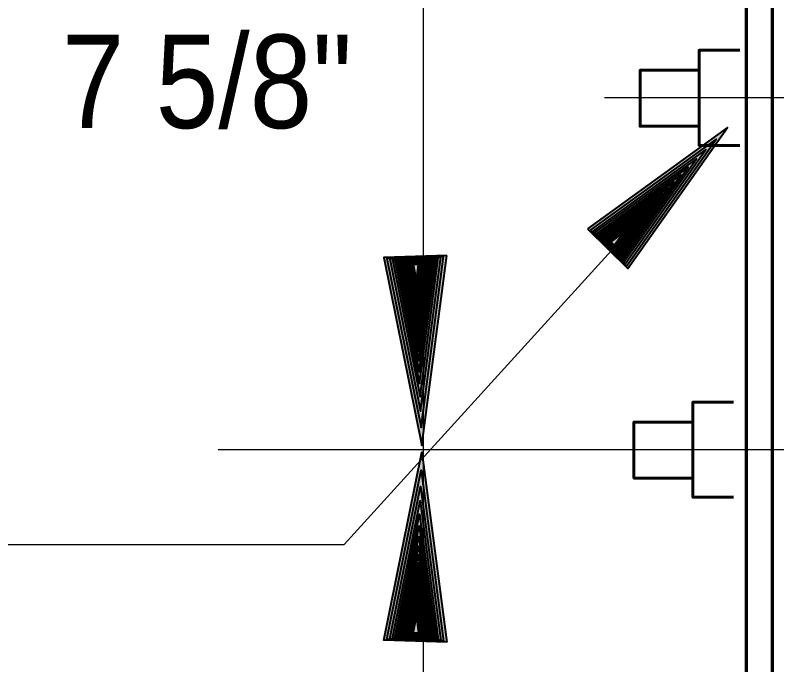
# Model space of a CAD drawing. Extents: x 856.9 to 891.7, y -2278.5 to -2254.7.
# Drawn here: x 863.098 to 864.144, y -2259.969 to -2259.076 of the extents above; entities that cross this region are included whole.
import ezdxf

# ---------------------------------------------------------------- set-up
doc = ezdxf.new("R2010")
doc.units = 0
doc.header["$LTSCALE"] = 0.051
doc.layers.add('1', color=7, linetype='Continuous', lineweight=70)
doc.layers.add('3', color=7, linetype='Continuous', lineweight=40)

msp = doc.modelspace()

# ---------------------------------------------------------------- hatches: boundary and pattern name
at = {"layer": '3'}
for points in [[(863.8845, -2259.36942), (863.94008, -2259.42425), (864.07683, -2259.23025), (864.07683, -2259.23025)], [(863.88808, -2259.37133), (863.938, -2259.42075), (864.06117, -2259.24625), (864.06117, -2259.24625)], [(863.89133, -2259.37317), (863.93617, -2259.41758), (864.047, -2259.2605), (864.047, -2259.2605)], [(863.89408, -2259.37475), (863.93442, -2259.41467), (864.03425, -2259.27333), (864.03425, -2259.27333)], [(863.8965, -2259.37625), (863.933, -2259.41208), (864.02275, -2259.28492), (864.02275, -2259.28492)], [(863.899, -2259.37742), (863.93175, -2259.40983), (864.0125, -2259.29533), (864.0125, -2259.29533)], [(863.90108, -2259.37875), (863.9305, -2259.40792), (864.00325, -2259.30475), (864.00325, -2259.30475)], [(863.903, -2259.37958), (863.92933, -2259.406), (863.99475, -2259.31325), (863.99475, -2259.31325)], [(863.90442, -2259.38067), (863.92858, -2259.40425), (863.98733, -2259.32083), (863.98733, -2259.32083)], [(863.90608, -2259.3815), (863.92783, -2259.40283), (863.98058, -2259.32767), (863.98058, -2259.32767)], [(863.9075, -2259.38225), (863.92683, -2259.40133), (863.9745, -2259.33392), (863.9745, -2259.33392)], [(863.90875, -2259.38308), (863.92608, -2259.40017), (863.96908, -2259.3395), (863.96908, -2259.3395)], [(863.90983, -2259.38358), (863.9255, -2259.39908), (863.964, -2259.3445), (863.964, -2259.3445)], [(863.91092, -2259.38408), (863.92492, -2259.39817), (863.95967, -2259.34875), (863.95967, -2259.34875)], [(863.91175, -2259.38458), (863.92442, -2259.39725), (863.95558, -2259.35283), (863.95558, -2259.35283)], [(863.9125, -2259.38508), (863.924, -2259.3965), (863.95217, -2259.35658), (863.95217, -2259.35658)], [(863.91333, -2259.38558), (863.92367, -2259.39583), (863.94892, -2259.35983), (863.94892, -2259.35983)], [(863.91392, -2259.386), (863.92317, -2259.39508), (863.94608, -2259.36275), (863.94608, -2259.36275)], [(863.9145, -2259.386), (863.92275, -2259.3945), (863.94333, -2259.36525), (863.94333, -2259.36525)], [(863.915, -2259.38633), (863.9225, -2259.39383), (863.94108, -2259.3675), (863.94108, -2259.3675)], [(863.91542, -2259.38633), (863.92225, -2259.39308), (863.93875, -2259.3695), (863.93875, -2259.3695)], [(863.91583, -2259.38683), (863.92192, -2259.39275), (863.93683, -2259.3715), (863.93683, -2259.3715)], [(863.91625, -2259.387), (863.92175, -2259.39233), (863.93533, -2259.37333), (863.93533, -2259.37333)], [(863.91658, -2259.38717), (863.9215, -2259.392), (863.93367, -2259.37475), (863.93367, -2259.37475)], [(863.69117, -2259.40608), (863.6045, -2259.409), (863.65667, -2259.66742), (863.65667, -2259.66742)], [(863.68683, -2259.40733), (863.60883, -2259.41008), (863.65583, -2259.64267), (863.65583, -2259.64267)], [(863.68292, -2259.40858), (863.61283, -2259.41092), (863.65508, -2259.62025), (863.65508, -2259.62025)], [(863.6795, -2259.40958), (863.61642, -2259.41175), (863.65442, -2259.60025), (863.65442, -2259.60025)], [(863.6765, -2259.4105), (863.61967, -2259.41242), (863.65383, -2259.58217), (863.65383, -2259.58217)], [(863.67358, -2259.41158), (863.6225, -2259.41317), (863.65333, -2259.56592), (863.65333, -2259.56592)], [(863.671, -2259.41225), (863.62508, -2259.41375), (863.65283, -2259.55117), (863.65283, -2259.55117)], [(863.66883, -2259.41308), (863.62733, -2259.41433), (863.65233, -2259.53792), (863.65233, -2259.53792)], [(863.66683, -2259.4135), (863.62942, -2259.41483), (863.65183, -2259.52617), (863.65183, -2259.52617)], [(863.66483, -2259.41425), (863.63117, -2259.41542), (863.6515, -2259.51533), (863.6515, -2259.51533)], [(863.66333, -2259.41467), (863.633, -2259.41575), (863.65125, -2259.50575), (863.65125, -2259.50575)], [(863.66175, -2259.41517), (863.63458, -2259.41617), (863.65083, -2259.49717), (863.65083, -2259.49717)], [(863.66042, -2259.41558), (863.63592, -2259.41642), (863.65058, -2259.48925), (863.65058, -2259.48925)], [(863.65917, -2259.41617), (863.63708, -2259.41667), (863.65042, -2259.48233), (863.65042, -2259.48233)], [(863.65808, -2259.41633), (863.63825, -2259.417), (863.65025, -2259.47608), (863.65025, -2259.47608)], [(863.65708, -2259.41675), (863.63925, -2259.41717), (863.64992, -2259.47042), (863.64992, -2259.47042)], [(863.65617, -2259.41692), (863.64008, -2259.4175), (863.64975, -2259.46533), (863.64975, -2259.46533)], [(863.65533, -2259.41708), (863.64092, -2259.41767), (863.64958, -2259.46075), (863.64958, -2259.46075)], [(863.65492, -2259.4175), (863.64175, -2259.41775), (863.64958, -2259.45667), (863.64958, -2259.45667)], [(863.65433, -2259.41767), (863.6425, -2259.41808), (863.6495, -2259.453), (863.6495, -2259.453)], [(863.65383, -2259.418), (863.64325, -2259.41842), (863.64967, -2259.44975), (863.64967, -2259.44975)], [(863.65325, -2259.418), (863.64383, -2259.41842), (863.6495, -2259.44667), (863.6495, -2259.44667)], [(863.65275, -2259.41817), (863.64425, -2259.4185), (863.64925, -2259.44392), (863.64925, -2259.44392)], [(863.65233, -2259.41842), (863.64475, -2259.41858), (863.64933, -2259.44158), (863.64933, -2259.44158)], [(863.69117, -2259.93775), (863.6045, -2259.93483), (863.65667, -2259.67642), (863.65667, -2259.67642)], [(863.68683, -2259.9365), (863.60883, -2259.93375), (863.65583, -2259.70117), (863.65583, -2259.70117)], [(863.68292, -2259.93525), (863.61283, -2259.93292), (863.65508, -2259.72358), (863.65508, -2259.72358)], [(863.6795, -2259.93425), (863.61642, -2259.93208), (863.65442, -2259.74358), (863.65442, -2259.74358)], [(863.6765, -2259.93333), (863.61967, -2259.93142), (863.65383, -2259.76167), (863.65383, -2259.76167)], [(863.67358, -2259.93225), (863.6225, -2259.93067), (863.65333, -2259.77792), (863.65333, -2259.77792)], [(863.671, -2259.93158), (863.62508, -2259.93008), (863.65283, -2259.79267), (863.65283, -2259.79267)], [(863.66883, -2259.93075), (863.62733, -2259.9295), (863.65233, -2259.80592), (863.65233, -2259.80592)], [(863.66683, -2259.93033), (863.62942, -2259.929), (863.65183, -2259.81767), (863.65183, -2259.81767)], [(863.66483, -2259.92958), (863.63117, -2259.92842), (863.6515, -2259.8285), (863.6515, -2259.8285)], [(863.66333, -2259.92917), (863.633, -2259.92808), (863.65125, -2259.83808), (863.65125, -2259.83808)], [(863.66175, -2259.92867), (863.63458, -2259.92767), (863.65083, -2259.84667), (863.65083, -2259.84667)], [(863.66042, -2259.92825), (863.63592, -2259.92742), (863.65058, -2259.85458), (863.65058, -2259.85458)], [(863.65917, -2259.92767), (863.63708, -2259.92717), (863.65042, -2259.8615), (863.65042, -2259.8615)], [(863.65808, -2259.9275), (863.63825, -2259.92683), (863.65025, -2259.86775), (863.65025, -2259.86775)], [(863.65708, -2259.92708), (863.63925, -2259.92667), (863.64992, -2259.87342), (863.64992, -2259.87342)], [(863.65617, -2259.92692), (863.64008, -2259.92633), (863.64975, -2259.8785), (863.64975, -2259.8785)], [(863.65533, -2259.92675), (863.64092, -2259.92617), (863.64958, -2259.88308), (863.64958, -2259.88308)], [(863.65492, -2259.92633), (863.64175, -2259.92608), (863.64958, -2259.88717), (863.64958, -2259.88717)], [(863.65433, -2259.92617), (863.6425, -2259.92575), (863.6495, -2259.89083), (863.6495, -2259.89083)], [(863.65383, -2259.92583), (863.64325, -2259.92542), (863.64967, -2259.89408), (863.64967, -2259.89408)], [(863.65325, -2259.92583), (863.64383, -2259.92542), (863.6495, -2259.89717), (863.6495, -2259.89717)], [(863.65275, -2259.92567), (863.64425, -2259.92533), (863.64925, -2259.89992), (863.64925, -2259.89992)], [(863.65233, -2259.92542), (863.64475, -2259.92525), (863.64933, -2259.90225), (863.64933, -2259.90225)]]:
    msp.add_hatch(color=256, dxfattribs=at).paths.add_polyline_path(points)

# ---------------------------------------------------------------- linework, layer by layer
at = {"layer": '1', "lineweight": 25}
for p, q in [((863.65917, -2260.57142), (863.65917, -2258.18292)), ((866.58492, -2259.18958), (863.90775, -2259.18958)), ((863.96775, -2259.34375), (863.55, -2259.80367)), ((865.83625, -2259.67342), (863.37692, -2259.67342)), ((862.061, -2259.80367), (863.55, -2259.80367))]:
    msp.add_line(p, q, dxfattribs=at)
at = {"layer": '1'}
msp.add_line((864.10225, -2258.59408), (864.10225, -2260.75108), dxfattribs=at)
msp.add_lwpolyline([(864.13817, -2258.59408), (864.13817, -2260.75108), (864.10225, -2260.75108)], dxfattribs=at)
at = {"layer": '1', "lineweight": 60}
for points in [[(864.0935, -2259.12392), (864.03775, -2259.12392), (864.03775, -2259.25475), (864.0935, -2259.25475)], [(864.03775, -2259.15142), (863.95675, -2259.15142), (863.95675, -2259.2285), (864.03775, -2259.2285)], [(864.085, -2259.60767), (864.02925, -2259.60767), (864.02925, -2259.7385), (864.085, -2259.7385)], [(864.02925, -2259.63517), (863.94825, -2259.63517), (863.94825, -2259.71225), (864.02925, -2259.71225)]]:
    msp.add_lwpolyline(points, dxfattribs=at)
at = {"layer": '3'}
for points in [[(863.8845, -2259.36942), (863.94008, -2259.42425), (864.07683, -2259.23025), (864.07683, -2259.23025)], [(863.88808, -2259.37133), (863.938, -2259.42075), (864.06117, -2259.24625), (864.06117, -2259.24625)], [(863.89133, -2259.37317), (863.93617, -2259.41758), (864.047, -2259.2605), (864.047, -2259.2605)], [(863.89408, -2259.37475), (863.93442, -2259.41467), (864.03425, -2259.27333), (864.03425, -2259.27333)], [(863.8965, -2259.37625), (863.933, -2259.41208), (864.02275, -2259.28492), (864.02275, -2259.28492)], [(863.899, -2259.37742), (863.93175, -2259.40983), (864.0125, -2259.29533), (864.0125, -2259.29533)], [(863.90108, -2259.37875), (863.9305, -2259.40792), (864.00325, -2259.30475), (864.00325, -2259.30475)], [(863.903, -2259.37958), (863.92933, -2259.406), (863.99475, -2259.31325), (863.99475, -2259.31325)], [(863.90442, -2259.38067), (863.92858, -2259.40425), (863.98733, -2259.32083), (863.98733, -2259.32083)], [(863.90608, -2259.3815), (863.92783, -2259.40283), (863.98058, -2259.32767), (863.98058, -2259.32767)], [(863.9075, -2259.38225), (863.92683, -2259.40133), (863.9745, -2259.33392), (863.9745, -2259.33392)], [(863.90875, -2259.38308), (863.92608, -2259.40017), (863.96908, -2259.3395), (863.96908, -2259.3395)], [(863.90983, -2259.38358), (863.9255, -2259.39908), (863.964, -2259.3445), (863.964, -2259.3445)], [(863.91092, -2259.38408), (863.92492, -2259.39817), (863.95967, -2259.34875), (863.95967, -2259.34875)], [(863.91175, -2259.38458), (863.92442, -2259.39725), (863.95558, -2259.35283), (863.95558, -2259.35283)], [(863.9125, -2259.38508), (863.924, -2259.3965), (863.95217, -2259.35658), (863.95217, -2259.35658)], [(863.91333, -2259.38558), (863.92367, -2259.39583), (863.94892, -2259.35983), (863.94892, -2259.35983)], [(863.91392, -2259.386), (863.92317, -2259.39508), (863.94608, -2259.36275), (863.94608, -2259.36275)], [(863.9145, -2259.386), (863.92275, -2259.3945), (863.94333, -2259.36525), (863.94333, -2259.36525)], [(863.915, -2259.38633), (863.9225, -2259.39383), (863.94108, -2259.3675), (863.94108, -2259.3675)], [(863.91542, -2259.38633), (863.92225, -2259.39308), (863.93875, -2259.3695), (863.93875, -2259.3695)], [(863.91583, -2259.38683), (863.92192, -2259.39275), (863.93683, -2259.3715), (863.93683, -2259.3715)], [(863.91625, -2259.387), (863.92175, -2259.39233), (863.93533, -2259.37333), (863.93533, -2259.37333)], [(863.91658, -2259.38717), (863.9215, -2259.392), (863.93367, -2259.37475), (863.93367, -2259.37475)], [(863.69117, -2259.40608), (863.6045, -2259.409), (863.65667, -2259.66742), (863.65667, -2259.66742)], [(863.68683, -2259.40733), (863.60883, -2259.41008), (863.65583, -2259.64267), (863.65583, -2259.64267)], [(863.68292, -2259.40858), (863.61283, -2259.41092), (863.65508, -2259.62025), (863.65508, -2259.62025)], [(863.6795, -2259.40958), (863.61642, -2259.41175), (863.65442, -2259.60025), (863.65442, -2259.60025)], [(863.6765, -2259.4105), (863.61967, -2259.41242), (863.65383, -2259.58217), (863.65383, -2259.58217)], [(863.67358, -2259.41158), (863.6225, -2259.41317), (863.65333, -2259.56592), (863.65333, -2259.56592)], [(863.671, -2259.41225), (863.62508, -2259.41375), (863.65283, -2259.55117), (863.65283, -2259.55117)], [(863.66883, -2259.41308), (863.62733, -2259.41433), (863.65233, -2259.53792), (863.65233, -2259.53792)], [(863.66683, -2259.4135), (863.62942, -2259.41483), (863.65183, -2259.52617), (863.65183, -2259.52617)], [(863.66483, -2259.41425), (863.63117, -2259.41542), (863.6515, -2259.51533), (863.6515, -2259.51533)], [(863.66333, -2259.41467), (863.633, -2259.41575), (863.65125, -2259.50575), (863.65125, -2259.50575)], [(863.66175, -2259.41517), (863.63458, -2259.41617), (863.65083, -2259.49717), (863.65083, -2259.49717)], [(863.66042, -2259.41558), (863.63592, -2259.41642), (863.65058, -2259.48925), (863.65058, -2259.48925)], [(863.65917, -2259.41617), (863.63708, -2259.41667), (863.65042, -2259.48233), (863.65042, -2259.48233)], [(863.65808, -2259.41633), (863.63825, -2259.417), (863.65025, -2259.47608), (863.65025, -2259.47608)], [(863.65708, -2259.41675), (863.63925, -2259.41717), (863.64992, -2259.47042), (863.64992, -2259.47042)], [(863.65617, -2259.41692), (863.64008, -2259.4175), (863.64975, -2259.46533), (863.64975, -2259.46533)], [(863.65533, -2259.41708), (863.64092, -2259.41767), (863.64958, -2259.46075), (863.64958, -2259.46075)], [(863.65492, -2259.4175), (863.64175, -2259.41775), (863.64958, -2259.45667), (863.64958, -2259.45667)], [(863.65433, -2259.41767), (863.6425, -2259.41808), (863.6495, -2259.453), (863.6495, -2259.453)], [(863.65383, -2259.418), (863.64325, -2259.41842), (863.64967, -2259.44975), (863.64967, -2259.44975)], [(863.65325, -2259.418), (863.64383, -2259.41842), (863.6495, -2259.44667), (863.6495, -2259.44667)], [(863.65275, -2259.41817), (863.64425, -2259.4185), (863.64925, -2259.44392), (863.64925, -2259.44392)], [(863.65233, -2259.41842), (863.64475, -2259.41858), (863.64933, -2259.44158), (863.64933, -2259.44158)], [(863.69117, -2259.93775), (863.6045, -2259.93483), (863.65667, -2259.67642), (863.65667, -2259.67642)], [(863.68683, -2259.9365), (863.60883, -2259.93375), (863.65583, -2259.70117), (863.65583, -2259.70117)], [(863.68292, -2259.93525), (863.61283, -2259.93292), (863.65508, -2259.72358), (863.65508, -2259.72358)], [(863.6795, -2259.93425), (863.61642, -2259.93208), (863.65442, -2259.74358), (863.65442, -2259.74358)], [(863.6765, -2259.93333), (863.61967, -2259.93142), (863.65383, -2259.76167), (863.65383, -2259.76167)], [(863.67358, -2259.93225), (863.6225, -2259.93067), (863.65333, -2259.77792), (863.65333, -2259.77792)], [(863.671, -2259.93158), (863.62508, -2259.93008), (863.65283, -2259.79267), (863.65283, -2259.79267)], [(863.66883, -2259.93075), (863.62733, -2259.9295), (863.65233, -2259.80592), (863.65233, -2259.80592)], [(863.66683, -2259.93033), (863.62942, -2259.929), (863.65183, -2259.81767), (863.65183, -2259.81767)], [(863.66483, -2259.92958), (863.63117, -2259.92842), (863.6515, -2259.8285), (863.6515, -2259.8285)], [(863.66333, -2259.92917), (863.633, -2259.92808), (863.65125, -2259.83808), (863.65125, -2259.83808)], [(863.66175, -2259.92867), (863.63458, -2259.92767), (863.65083, -2259.84667), (863.65083, -2259.84667)], [(863.66042, -2259.92825), (863.63592, -2259.92742), (863.65058, -2259.85458), (863.65058, -2259.85458)], [(863.65917, -2259.92767), (863.63708, -2259.92717), (863.65042, -2259.8615), (863.65042, -2259.8615)], [(863.65808, -2259.9275), (863.63825, -2259.92683), (863.65025, -2259.86775), (863.65025, -2259.86775)], [(863.65708, -2259.92708), (863.63925, -2259.92667), (863.64992, -2259.87342), (863.64992, -2259.87342)], [(863.65617, -2259.92692), (863.64008, -2259.92633), (863.64975, -2259.8785), (863.64975, -2259.8785)], [(863.65533, -2259.92675), (863.64092, -2259.92617), (863.64958, -2259.88308), (863.64958, -2259.88308)], [(863.65492, -2259.92633), (863.64175, -2259.92608), (863.64958, -2259.88717), (863.64958, -2259.88717)], [(863.65433, -2259.92617), (863.6425, -2259.92575), (863.6495, -2259.89083), (863.6495, -2259.89083)], [(863.65383, -2259.92583), (863.64325, -2259.92542), (863.64967, -2259.89408), (863.64967, -2259.89408)], [(863.65325, -2259.92583), (863.64383, -2259.92542), (863.6495, -2259.89717), (863.6495, -2259.89717)], [(863.65275, -2259.92567), (863.64425, -2259.92533), (863.64925, -2259.89992), (863.64925, -2259.89992)], [(863.65233, -2259.92542), (863.64475, -2259.92525), (863.64933, -2259.90225), (863.64933, -2259.90225)]]:
    msp.add_lwpolyline(points, close=True, dxfattribs=at)

# ---------------------------------------------------------------- texts
at = {"layer": '1', "width": 0.9}
msp.add_text('7 5/8"', height=0.1286, dxfattribs=at).set_placement((863.16217, -2259.23108))

doc.saveas('drawing.dxf')
